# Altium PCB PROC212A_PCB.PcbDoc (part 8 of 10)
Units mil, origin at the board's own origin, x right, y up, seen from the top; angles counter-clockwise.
Board outline 3032.48 x 3598.78 mil, 4 copper layers (Top Layer, L2_GND1, L3_PWR1, Bottom Layer), stack 60.58 mil thick; 432 components, 310 nets, 7775 pads, 1236 vias.
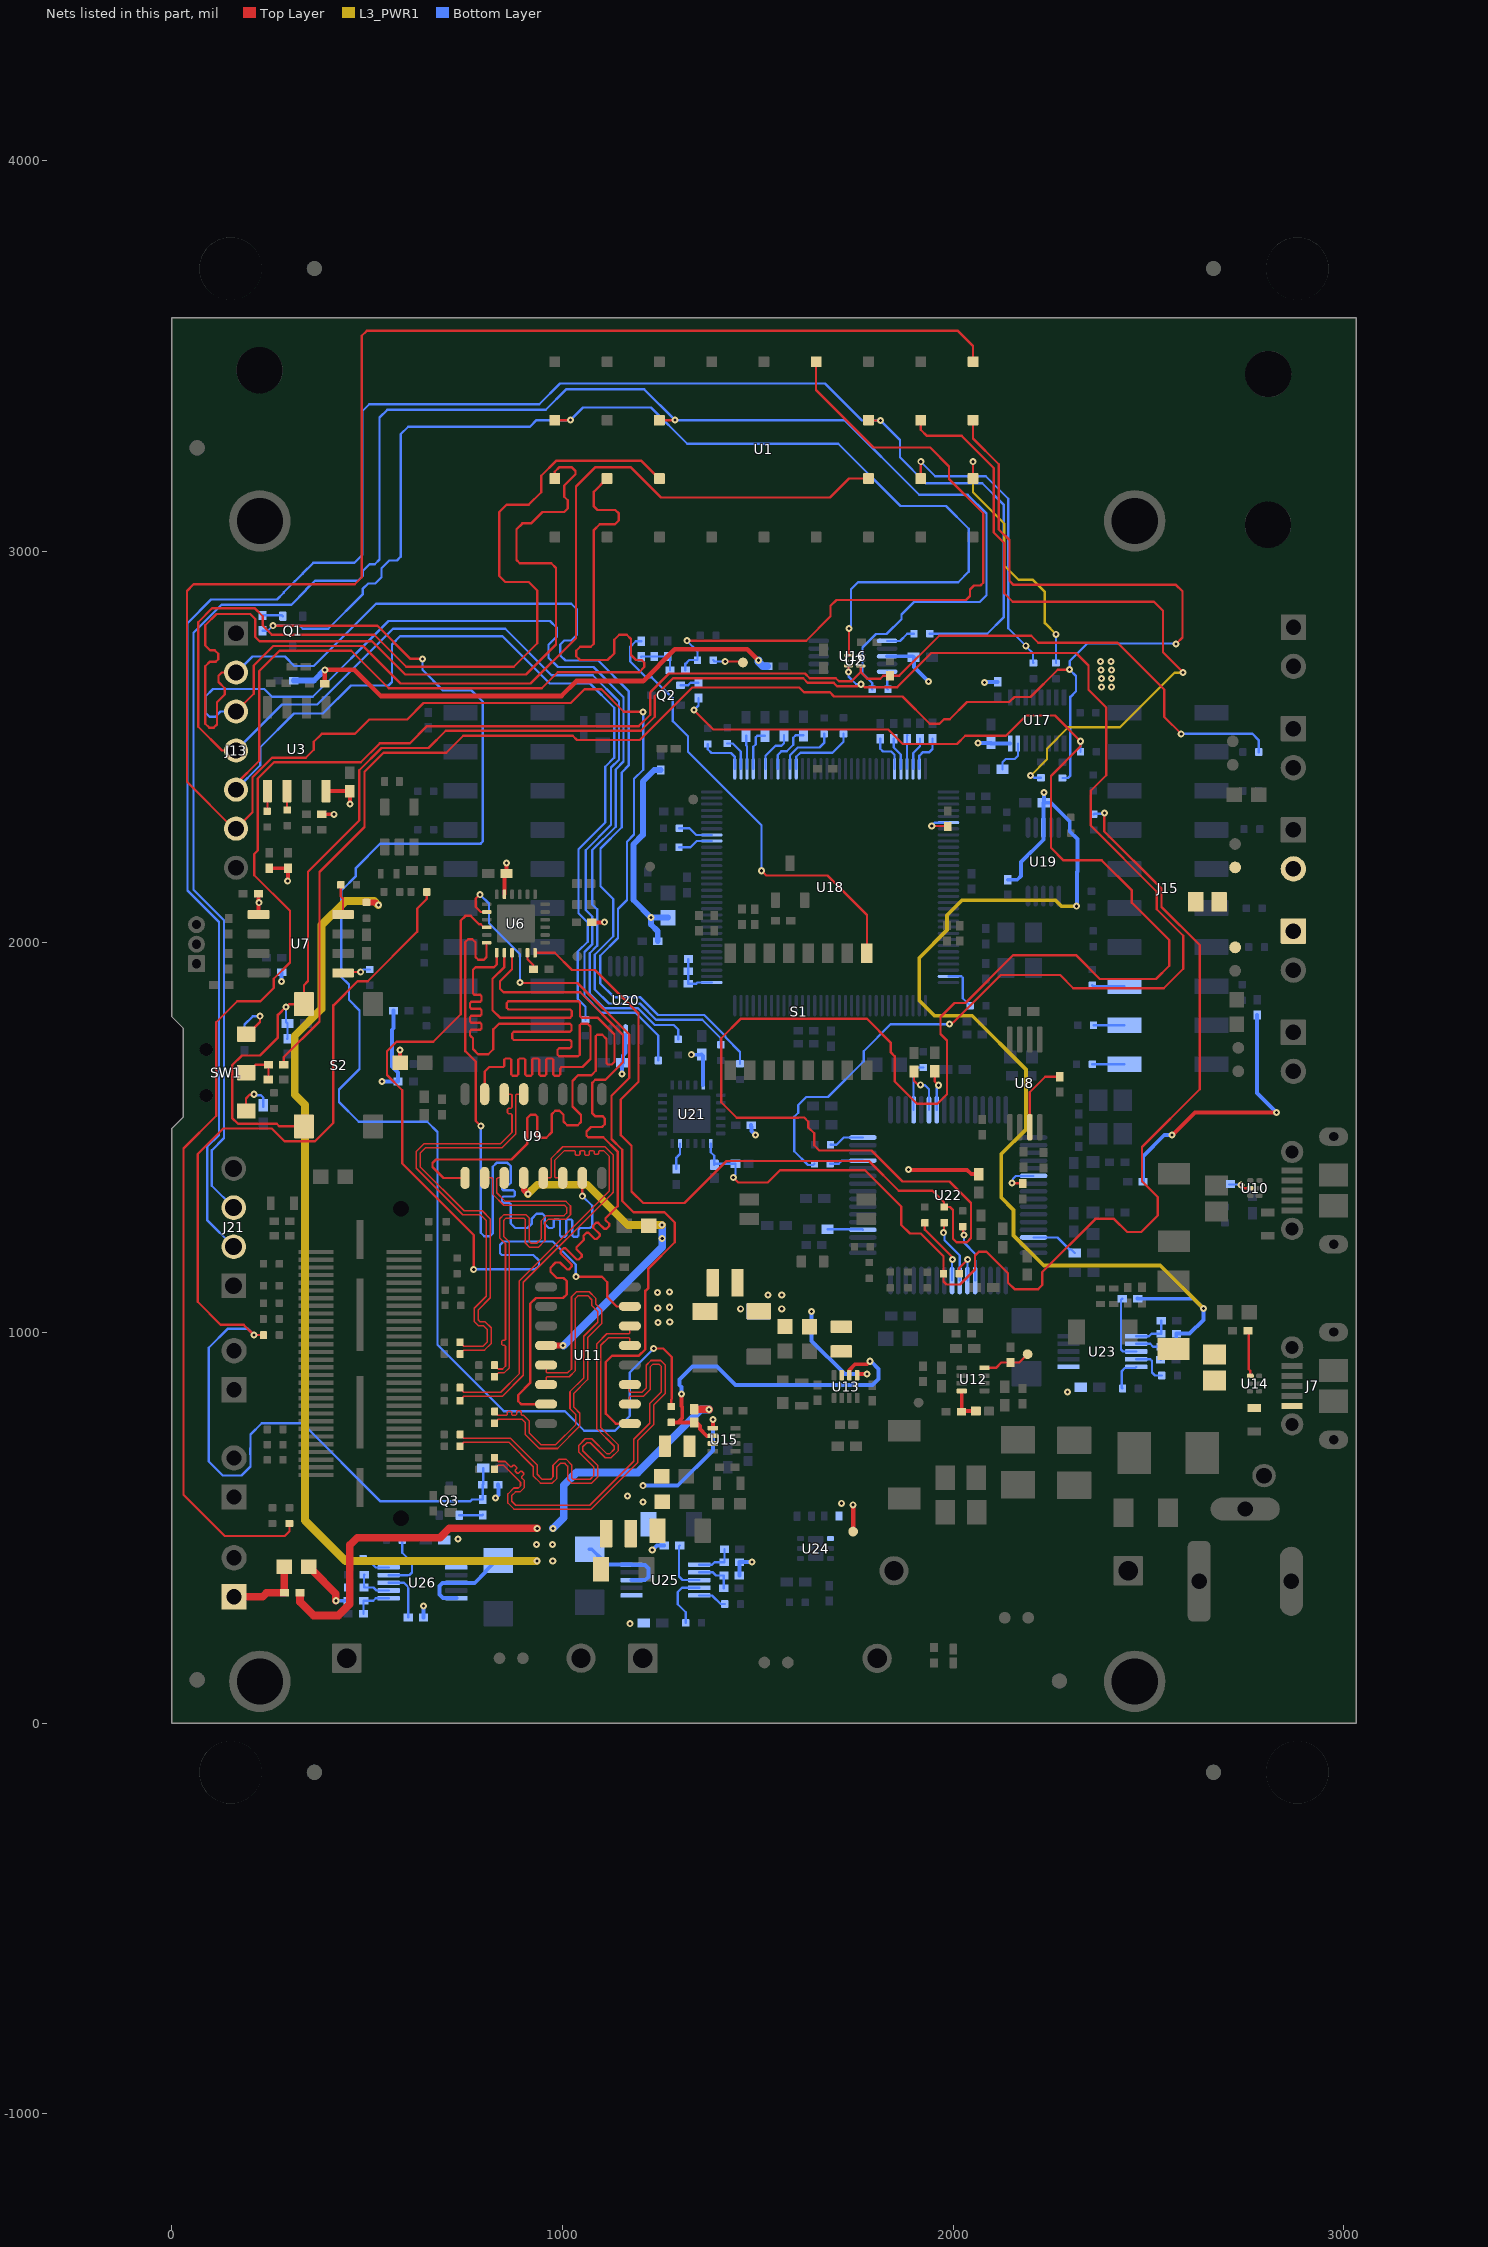
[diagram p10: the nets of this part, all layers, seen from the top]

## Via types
v1: diameter 18, hole 8, Top Layer to Bottom Layer, tented both sides, 1224 vias
v2: diameter 19.68, hole 7.87, Top Layer to Bottom Layer, tented both sides, 10 vias
v3: diameter 19.68, hole 7.87, Top Layer to Bottom Layer, 2 vias

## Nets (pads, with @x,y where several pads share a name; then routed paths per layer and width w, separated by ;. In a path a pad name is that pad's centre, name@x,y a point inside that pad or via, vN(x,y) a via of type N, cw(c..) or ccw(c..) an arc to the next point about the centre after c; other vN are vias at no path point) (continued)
NetJ15_15: J15.15 R156.2 | length 83.3
  Bottom Layer w5.9: R156.2@2356.43,1889.43 2358.64,1887.22 J15.15@2438.83,1887.22
NetJ15_17: J15.17 R163.2 | length 79.1
  Bottom Layer w5.9: R163.2@2359.71,1787.22 J15.17@2438.83,1787.22
NetJ15_19: J15.19 R173.2 | length 82.3
  Bottom Layer w5.9: R173.2@2356.49,1687.21 J15.19@2438.83,1687.22
NetJ24_1: J24.1 L7.1 R92.1 | length 200.5
  Top Layer w20: J24.1@158.99,323.6 232.19,323.6 242.44,333.86 288.16,333.86 L7.1@288.32,334.01 287.71,334.62 R92.1@287.71,400.57
NetQ1_1: Q1.1 R96.1 | length 52.8
  Bottom Layer w5.9: R96.1@231.93,2836.45 281.94,2836.45 Q1.1@283.94,2834.44
NetQ2_1: Q2.1 R109.1 | length 48.4
  Bottom Layer w5.9: Q2.1@1302.39,2657.8 1321.63,2657.8 1327.71,2663.87 1347.33,2663.87 R109.1@1348.02,2664.55
NetQ3_1: Q3.1 R203.2 | length 60.2
  Bottom Layer w5.9: Q3.1@735.68,532.71 794.84,532.71 R203.2@795.54,533.42
NetR5_1: R5.1 U18.70 | length 86.9
  Top Layer w5.9: v1(1945.42,2297.41) 1985,2297.41 R5.1@1986.29,2296.12
  Bottom Layer w5.9: v1(1945.42,2297.41) 1953.9,2305.89 U18.70@1987.37,2305.89
NetR6_1: R6.1 U3.6 | length 48.3
  Top Layer w5.9: U3.6@294.65,2386.58 294.65,2338.8 R6.1@295.02,2338.42
NetR7_1: R7.1 U3.5 | length 51.9
  Top Layer w5.9: R7.1@243.74,2335.07 244.65,2335.98 U3.5@244.65,2386.58
NetR15_1: R15.1 U7.4 | length 78.5
  Top Layer w5.9: R15.1@432.28,2146.71 432.28,2117.55 438.19,2111.64 U7.4@438.19,2070.7
NetR29_2: R29.2 R31.2 SW1.2 | length 103.5
  Top Layer w5.9: SW1.2@190.18,1665.84 194.12,1665.84 210.86,1682.57 210.86,1682.82 214.31,1686.28 R29.2@246.97,1686.28 246.97,1648.55 R31.2@246.71,1648.29
NetR30_2: R30.2 U8.3 | length 182.5
  Top Layer w5.9: U8.3@2196.46,1526.03 2196.46,1615.75 2235.92,1655.22 R30.2@2272.89,1655.22
NetR39_1: R39.1 U22.23 | length 165.6
  Top Layer w5.9: v1(1975.85,1255.9) 1976.6,1256.64 1976.6,1280.72 R39.1@1977.34,1281.47
  Bottom Layer w5.9: v1(1975.85,1255.9) 1978.03,1253.73 1978.03,1236.42 2017.07,1197.37 U22.23@2017.07,1133.54
NetR40_1: R40.1 U22.24 | length 177.1
  Top Layer w5.9: R40.1@1927.81,1281.24 1927.81,1263.47 1995.76,1195.51 1995.76,1189.56 v1(1998.08,1187.24)
  Bottom Layer w5.9: U22.24@1997.38,1133.54 1997.38,1186.55 v1(1998.08,1187.24)
NetR42_1: R42.1 U22.21 | length 151.1
  Top Layer w5.9: R42.1@2024.65,1271.49 2026.27,1269.88 2026.27,1251.26 v1(2027.89,1249.64)
  Bottom Layer w5.9: v1(2027.89,1249.64) 2027.89,1230.66 2056.25,1202.3 2056.25,1184.14 2056.44,1183.95 U22.21@2056.44,1133.54
NetR52_1: R52.1 U22.22 | length 99.1
  Top Layer w5.9: R52.1@2015.84,1151.06 2015.84,1165.63 v1(2037.45,1187.24)
  Bottom Layer w5.9: U22.22@2036.75,1133.54 2036.75,1186.55 v1(2037.45,1187.24)
NetR63_2: R63.2 U14.1 | length 117.8
  Top Layer w5.9: R63.2@2755.13,1004.53 2757.07,1002.59 2757.07,906.25 2760.99,902.33 U14.1@2760.99,889.18
NetR97_1: R97.1 U16.6 | length 76.5
  Bottom Layer w5.9: U16.6@1831.11,2771.15 1864.24,2771.15 1882.62,2789.54 R97.1@1900.04,2789.54
NetR99_2: R99.2 R100.2 R101.1 R106.2 | length 105.8
  Bottom Layer w5.9: R101.1@1201.44,2730.83 1201.88,2731.28 R99.2@1235.04,2731.28 1269.8,2731.28 R100.2@1269.86,2731.22 1275.26,2725.82 R106.2@1275.26,2696.32
NetR110_1: R110.1 U16.10 | length 46
  Bottom Layer w5.9: U16.10@1831.11,2692.41 1831.11,2649.39 R110.1@1833.2,2647.3
NetR112_1: R112.1 U18.40 | length 132.6
  Bottom Layer w5.9: U18.40@1551.19,2443.77 1551.19,2479.26 1560.37,2488.44 1573.92,2488.44 1590.9,2505.43 1590.9,2523.29 1597.5,2529.89 R112.1@1616.86,2529.89
NetR113_1: R113.1 U18.38 | length 114.4
  Bottom Layer w5.9: U18.38@1519.78,2443.69 1519.78,2477.11 1545.52,2502.86 1560.8,2502.86 1566.92,2508.99 R113.1@1566.92,2529.58
NetR114_1: R114.1 U18.36 | length 108.8
  Bottom Layer w5.9: U18.36@1488.28,2443.69 1488.28,2499.91 1495.15,2506.77 1495.15,2525.12 1498.6,2528.57 R114.1@1518.21,2528.57
NetR115_1: R115.1 U18.35 | length 85.7
  Bottom Layer w5.9: R115.1@1470.11,2528.57 1470.11,2503.71 1472.4,2501.41 U18.35@1472.4,2443.82
NetR117_2: R117.2 U18.43 | length 188.2
  Bottom Layer w5.9: U18.43@1598.52,2443.69 1598.54,2474.3 1609.22,2484.97 1691.35,2484.97 1719.52,2513.15 R117.2@1719.52,2533.72
NetR118_2: R118.2 U18.42 | length 158.4
  Bottom Layer w5.9: U18.42@1582.52,2443.93 1582.52,2478.54 1602.09,2498.1 1658.22,2498.1 1669.81,2509.69 R118.2@1669.81,2533.34
NetR119_1: R119.1 U18.61 | length 86.2
  Bottom Layer w5.9: U18.61@1881.9,2443.77 1881.9,2528.38 R119.1@1882.99,2529.47
NetR120_1: R120.1 U18.62 | length 84
  Bottom Layer w5.9: U18.62@1898.01,2443.97 1898.01,2483.91 1915.24,2501.14 R120.1@1915.24,2520.87
NetR121_1: R121.1 U18.63 | length 100.5
  Bottom Layer w5.9: U18.63@1913.71,2443.93 1913.71,2477.23 1922.93,2486.44 1939.57,2486.44 1947.45,2494.32 R121.1@1947.45,2520.66
NetR122_1: R122.1 U18.60 | length 84.2
  Bottom Layer w5.9: R122.1@1848.12,2520.45 1848.12,2498.21 1866.19,2480.14 U18.60@1866.23,2443.69
NetR123_2: R123.2 U18.59 | length 103.8
  Bottom Layer w5.9: R123.2@1813.42,2520.34 1813.42,2494.93 1820.59,2487.77 1841.73,2487.77 1850.08,2479.43 1850.08,2469.12 U18.59@1850.11,2444.13
NetR124_1: R124.1 U18.34 | length 87
  Bottom Layer w5.9: R124.1@1422.04,2508.33 1435.68,2508.33 1456.21,2487.81 1456.21,2469.28 1456.41,2469.08 1456.41,2444.07 U18.34@1456.78,2443.69
NetR125_1: R125.1 U18.33 | length 121.2
  Bottom Layer w5.9: R125.1@1371.68,2506.96 1371.68,2493.88 1381.57,2483.99 1431.64,2483.99 1440.68,2474.95 1440.68,2444.05 U18.33@1440.92,2443.8
NetR131_2: R131.2 U17.15 | length 96.1
  Bottom Layer w5.9: R131.2@2126.41,2442.26 2126.41,2460.35 2134.91,2468.85 2157.78,2468.85 2166.01,2477.08 U17.15@2166.01,2508.55
NetR139_1: R139.1 U18.25 | length 89.9
  Bottom Layer w5.9: R139.1@1299.13,2291.52 1325.07,2291.52 1342.19,2274.4 U18.25@1381.98,2274.4
NetR142_1: R142.1 U18.24 | length 90.1
  Bottom Layer w5.9: R142.1@1298.47,2242.72 1327.85,2242.72 1343.77,2258.65 U18.24@1381.98,2258.65
NetR155_1: R155.1 U7.1 | length 72
  Top Layer w5.9: U7.1@438.19,1920.7 440.78,1923.3 v1(483.37,1923.3)
  Bottom Layer w5.9: v1(483.37,1923.3) 490.03,1929.96 R155.1@506.32,1929.96
NetR160_2: R160.2 U18.95 | length 117.5
  Bottom Layer w5.9: U18.95@1988.28,1912.19 2021.12,1912.19 2024.58,1908.74 2024.58,1856.11 R160.2@2043.8,1836.89
NetR165_1: R165.1 SW1.1 | length 148.3
  Top Layer w5.9: SW1.1@180.18,1764.97 194.83,1764.97 225.46,1795.6 v1(225.46,1810.24)
  Bottom Layer w5.9: R165.1@185.74,1761.73 185.74,1788.77 207.21,1810.24 v1(225.46,1810.24)
NetR176_2: R176.2 SW1.3 | length 108.5
  Top Layer w5.9: SW1.3@190.18,1567.41 189.47,1568.12 189.47,1599.76 198.56,1608.85 208.53,1608.85 v1(210.06,1610.39)
  Bottom Layer w5.9: v1(210.06,1610.39) 212.38,1608.07 227.76,1608.07 233.75,1602.07 R176.2@233.75,1578.3
NetR183_2: R183.2 U10.5 | length 57.1
  Top Layer w5.9: v1(2736.73,1377.79) 2737.45,1377.79 2745.22,1370.01 U10.5@2760.01,1370.01
  Bottom Layer w5.9: R183.2@2706.77,1379.46 2735.06,1379.46 v1(2736.73,1377.79)
NetR187_1: R187.1 U22.36 | length 90.8
  Bottom Layer w5.9: R187.1@1678.68,1264.59 1767.91,1264.59 U22.36@1769.04,1263.46
NetR191_2: R191.2 U23.3 | length 172.6
  Bottom Layer w5.9: R191.2@2433.28,1087.16 2430.11,1084 2430.11,956.63 2435.07,951.67 U23.3@2468.83,951.67
NetR193_2: R193.2 R194.1 U23.1 | length 99.9
  Bottom Layer w5.9: U23.1@2468.83,991.04 2501.72,991.04 2508.06,997.38 R194.1@2532.69,997.38 2533.25,997.94 R193.2@2533.25,1030.57
NetR195_1: R195.1 R196.2 U23.2 | length 99.5
  Bottom Layer w5.9: U23.2@2468.83,971.36 2504.76,971.36 2512.57,963.55 R195.1@2532.12,963.55 2532.12,931.62 R196.2@2531.38,930.88
NetR197_1: R197.1 U23.4 | length 99.9
  Bottom Layer w5.9: U23.4@2468.83,931.99 2504.83,931.99 2509.17,927.65 2509.17,897.9 2516.78,890.28 R197.1@2534.03,890.28
NetR198_1: R198.1 U23.5 | length 86.7
  Bottom Layer w5.9: R198.1@2434.04,857.02 2432.17,858.89 2432.17,901.95 2439.56,909.35 2465.88,909.35 U23.5@2468.83,912.3
NetR204_1: R204.1 U26.4 | length 156.4
  Bottom Layer w5.9: U26.4@554.85,379.2 608.1,379.2 614.79,385.89 614.79,411.21 589.64,436.35 R204.1@589.64,469.17
NetR206_2: R206.2 U25.3 | length 136.3
  Bottom Layer w5.9: R206.2@1299.97,455.23 1298.1,453.36 1298.1,375.38 1306.92,366.55 U25.3@1350.1,366.55
NetR207_2: R207.2 R210.1 U25.1 | length 99.9
  Bottom Layer w5.9: U25.1@1350.1,405.92 1382.99,405.92 1389.33,412.26 R210.1@1413.96,412.26 1414.52,412.81 R207.2@1414.52,445.45
NetR209_1: R209.1 U26.5 | length 74.3
  Bottom Layer w5.9: R209.1@489.65,420.9 499.84,420.9 521.86,398.88 U26.5@554.85,398.88
NetR211_2: R211.2 R215.1 U26.2 | length 101
  Bottom Layer w5.9: R215.1@491.56,347.64 515.84,347.64 523.64,339.83 U26.2@554.85,339.83 ; R211.2@492.3,380.3 491.56,379.56 491.56,351.15 R215.1@495.07,347.64
NetR212_1: R212.1 R216.2 U25.2 | length 99.5
  Bottom Layer w5.9: U25.2@1350.1,386.24 1385.05,386.24 1392.86,378.43 R212.1@1413.39,378.43 1412.65,377.69 R216.2@1412.65,345.76
NetR218_1: R218.1 U25.5 | length 74.3
  Bottom Layer w5.9: U25.5@1350.1,327.18 1383.09,327.18 1405.11,305.16 R218.1@1415.3,305.16
NetR219_1: R219.1 R220.2 U26.1 | length 99.9
  Bottom Layer w5.9: R220.2@490.43,280.61 490.43,313.25 R219.1@490.99,313.8 515.62,313.8 521.96,320.14 U26.1@554.85,320.14
NetR221_2: R221.2 U26.3 | length 132.3
  Bottom Layer w5.9: U26.3@554.85,359.51 593.94,359.51 604.98,348.47 R221.2@604.98,270.83
NetR222_1: R222.1 U25.4 | length 147.2
  Bottom Layer w5.9: R222.1@1315.31,256.9 1315.31,284.03 1294.87,304.47 1294.87,335.88 1305.85,346.87 U25.4@1350.1,346.87
NRESET: R74.2 R96.2 U1.15 U2.4 | length 6837.2
  Top Layer w5.9: v1(258.31,2810.09) 526.14,2810.09 611.14,2725.09 v1(641.31,2725.09) ; U1.15@980.3,3336.41 v1(1020.21,3336.41) ; v1(1233.5,959.31) 1258.15,959.31 1279.86,937.6 1279.86,830.34 1278.6,829.07 R74.2@1278.6,810.73 ; U2.4@1732.16,2734.55 1733.18,2734.55 1733.58,2734.95 v1(1733.58,2803.12)
  Bottom Layer w5.9: R96.2@231.93,2797.08 245.29,2797.08 v1(258.31,2810.09) 326.94,2810.09 334.94,2802.09 400.31,2802.09 488.17,2889.96 488.17,2904.05 502.36,2918.24 520.64,2918.24 536.42,2934.02 536.42,2957.11 556.45,2977.14 576.29,2977.14 586.09,2986.94 586.09,3300.63 604.77,3319.3 916.6,3319.3 933.71,3336.41 v1(1020.21,3336.41) 1052.4,3368.6 1226.63,3368.6 1319.33,3275.9 1706,3275.9 1865.32,3116.58 1981.7,3116.58 2040.12,3058.16 2040.12,2948.52 2012.97,2921.37 1756.74,2921.37 1738.8,2903.43 1738.8,2811.62 1733.58,2806.4 v1(1733.58,2803.12) ; v1(641.31,2725.09) 641.31,2697.09 694.1,2644.3 767.1,2644.3 795.67,2615.73 795.67,2257.46 790.31,2252.09 533.19,2252.09 471,2189.9 471,2169.05 433.56,2131.61 433.56,1910.84 453.31,1891.09 453.31,1852.09 480.31,1825.09 480.31,1675.09 427.79,1622.58 427.79,1590.61 478.16,1540.24 653.57,1540.24 679.74,1514.07 679.74,969.21 849.82,799.13 1005.47,799.13 1055.6,748.99 1134.55,748.99 1172.35,786.8 1172.35,898.16 v1(1233.5,959.31)
NRST_FTDI: R180.1 U22.45 | length 87.2
  Bottom Layer w5.9: R180.1@1685.35,1432.23 1707.39,1432.23 1715.79,1440.63 U22.45@1769.04,1440.63
PGOOD: R16.1 R62.1 R201.2 R202.1 R203.1 | length 3114.3
  Top Layer w5.9: R62.1@234.25,993.83 210,993.83 v1(209.86,993.96) 183.56,1020.27 124.63,1020.27 66.03,1078.86 66.03,1457.38 131.39,1522.75 255.82,1522.75 288.86,1489.71 365.56,1489.71 413.37,1537.52 413.37,1837.9 475.45,1899.98 501.22,1899.98 627.72,2026.47 627.72,2085.46 652.59,2110.33 R16.1@652.59,2128.4
  Bottom Layer w5.9: v1(209.86,993.96) 193.49,1010.34 143.25,1010.34 94.16,961.25 94.16,670.4 130.27,634.3 177.98,634.3 200.92,657.24 200.92,688.91 200.82,689.01 200.82,703.88 200.92,703.97 200.92,739.14 229.72,767.93 334.03,767.93 534.01,567.96 763.58,567.96 768.41,572.79 R203.1@795.54,572.79 795.74,572.98 R202.1@795.74,610.79 797.12,612.18 R201.2@797.12,653.22
PMIC_CLK_OUT: R102.2 TP1.1 | length 78.5
  Top Layer w5.9: v1(1416.62,2718.66) 1459.22,2718.66 TP1.1@1462.02,2715.86
  Bottom Layer w5.9: R102.2@1386.04,2722.01 1389.4,2718.66 v1(1416.62,2718.66)
PMIC_CLK_OUT_SOP1: R102.1 R106.1 U1.4 | length 1786.3
  Top Layer w5.9: v1(1318.33,2771.66) 1623.87,2771.66 1686.31,2834.09 1686.31,2861.09 1701.31,2876.09 2033.31,2876.09 2043.36,2886.14 2043.36,2902.53 2053.87,2913.04 2070.26,2913.04 2077.31,2920.09 2077.31,3097.86 1989.62,3185.55 1989.62,3217.78 1941.31,3266.09 1796.31,3266.09 1649.16,3413.24 1649.16,3485.58 U1.4@1649.59,3486.02
  Bottom Layer w5.9: R106.1@1314.63,2696.32 1314.63,2712.34 1324.31,2722.01 R102.1@1345.69,2722.01 1345.69,2744.3 v1(1318.33,2771.66)
PRESENCE_INDICATION_GPIO: R39.2 R109.2 R126.1 U6.18 | length 6491.7
  Top Layer w5.9: U6.18@929.94,1972.77 980,1972.77 1024.02,1928.75 1083.19,1928.75 1194.77,1817.17 1194.77,1642.35 1149.33,1596.91 1149.33,1505.75 1176.78,1478.31 1176.78,1361.6 1206.48,1331.89 1312.23,1331.89 1419.79,1439.45 1784.48,1439.45 1860.71,1363.23 1947.3,1363.23 1976.86,1333.67 1976.86,1322.3 R39.2@1977.34,1321.82 1992.31,1321.82 2000.01,1314.13 2000.01,1240.32 2008.63,1231.69 2035.32,1231.69 2045.84,1242.21 2045.84,1331.98 1990.79,1387.03 1870.57,1387.03 1791.12,1466.48 1657.62,1466.48 1644.28,1479.82 1644.28,1510.77 1629.45,1525.59 1629.45,1540.15 1618.93,1550.66 1604.06,1550.66 1603.41,1550.01 1446.11,1550.01 1406.37,1589.76 1406.37,1753.6 1456.81,1804.04 1779.05,1804.04 1840.05,1743.04 1840.05,1718.29 1850.36,1707.98 1850.36,1643.53 1908.15,1585.74 1959.65,1585.74 1984.39,1610.47 1984.39,1748.07 1967.68,1764.78 1967.68,1808.11 2003.4,1843.83 2031.56,1843.83 2154.35,1966.62 2314.65,1966.62 2375.57,1905.7 2519.55,1905.7 2553.37,1939.52 2553.37,2005.12 2457.83,2100.66 2457.83,2132.19 2380.79,2209.23 2282.77,2209.23 2250.58,2241.42 2250.58,2425.31 2326.5,2501.23 2326.5,2515.09 2325.65,2515.09 2260.75,2579.98 2187.08,2579.98 2135.26,2528.16 2031.38,2528.16 2010.22,2507.01 1871.39,2507.01 1833.99,2544.41 1385.73,2544.41 v1(1336.34,2593.8)
  Bottom Layer w5.9: v1(1336.34,2593.8) 1348.02,2605.48 R109.2@1348.02,2625.18 ; R126.1@2326.42,2487.22 2326.42,2514.16 v1(2326.5,2514.24)
RADAR_LVDS_0M: R87.2 U11.11 | length 1012.5
  Top Layer w4: R87.2@826.12,650.09 826.12,650.58 835.63,660.09 849.56,660.09 892.44,617.21 892.44,607.64 886.99,602.18 875.36,602.18 860.22,587.05 860.22,563.92 875.86,548.28 1073.69,548.28 1192.13,666.72 1192.13,723.13 1233.1,764.1 1233.1,814.24 1263.15,844.29 1263.15,917.18 1251.56,928.77 1226.59,928.77 1214.23,916.41 1214.23,858.23 1203.41,847.41 1173.64,847.41 1171.3,849.75 1171.3,865.9 U11.11@1172.48,867.07
RADAR_LVDS_0P: R85.2 U11.10 | length 1012.5
  Top Layer w4: R85.2@826.12,680.09 826.12,679.6 835.63,670.09 853.71,670.09 859.44,664.36 866.87,656.92 870.27,656.92 873.85,660.5 877.24,660.5 882.33,655.41 882.33,652.01 878.75,648.44 878.75,645.04 883.84,639.95 887.24,639.95 892.33,645.04 895.72,645.04 900.81,639.95 900.81,636.56 895.72,631.47 895.72,628.07 902.44,621.35 902.44,610.19 902.44,603.49 891.13,592.18 879.5,592.18 870.22,582.9 870.22,568.07 880,558.28 1069.54,558.28 1182.13,670.86 1182.13,727.27 1223.1,768.25 1223.1,818.38 1253.15,848.43 1253.15,913.04 1247.41,918.77 1230.73,918.77 1224.23,912.27 1224.23,854.09 1207.55,837.41 1173.64,837.41 1171.3,835.06 1171.3,818.25 U11.10@1172.48,817.07
RADAR_LVDS_1M: R83.2 U11.13 | length 1100.4
  Top Layer w4: R83.2@737.69,709.15 737.69,709.64 747.2,719.15 863.11,719.15 925.36,656.9 925.36,633.11 943.6,614.87 973.97,614.87 985.66,626.56 985.66,656.36 994.62,665.32 1005.91,665.32 1009.8,661.43 1013.32,657.91 1013.32,624.53 1022.98,614.87 1075.15,614.87 1090.43,630.14 1090.43,659.66 1052.14,697.94 1052.14,707.86 1062.6,718.32 1070.79,718.32 1109.6,679.51 1124.47,679.51 1142.23,697.27 1142.23,713.31 1098.14,757.41 1098.14,967.52 1117.69,987.07 1130.05,987.07 1170.14,987.07 1172.48,984.73 U11.13@1172.48,967.07
RADAR_LVDS_1P: R81.2 U11.14 | length 1100.4
  Top Layer w4: R81.2@737.69,739.15 737.69,738.65 747.2,729.15 867.25,729.15 935.36,661.04 935.36,637.25 947.74,624.87 969.82,624.87 975.66,630.7 975.66,660.5 990.47,675.32 1010.06,675.32 1023.32,662.05 1023.32,628.67 1027.12,624.87 1071.01,624.87 1080.43,634.28 1080.43,655.52 1042.14,693.8 1042.14,712 1058.45,728.32 1074.93,728.32 1113.74,689.51 1120.32,689.51 1132.23,701.41 1132.23,709.17 1088.14,753.26 1088.14,971.66 1113.55,997.07 1134.19,997.07 1170.14,997.07 1172.48,999.42 U11.14@1172.48,1017.07
RADAR_LVDS_2M: R71.2 U9.5 | length 1097.2
  Top Layer w4: R71.2@737.7,827.41 737.7,827.9 747.2,837.41 846.22,837.41 899.79,890.98 899.79,1013.42 899.79,1128.86 1124.27,1353.34 1130.13,1359.2 1130.13,1454.92 1108.86,1476.19 1100.93,1476.19 1016.34,1476.19 1000.91,1476.19 970.64,1445.92 970.64,1398.55 968.3,1396.21 U9.5@950.64,1396.21
RADAR_LVDS_2P: R69.2 U9.6 | length 1097.2
  Top Layer w4: R69.2@737.7,857.41 737.7,856.92 747.2,847.41 842.08,847.41 889.79,895.12 889.79,1009.27 889.79,1133.01 1120.13,1363.34 1120.13,1450.77 1104.72,1466.19 1100.93,1466.19 1095.14,1466.19 1092.74,1463.79 1092.74,1459.3 1090.34,1456.9 1083.14,1456.9 1080.74,1459.3 1080.74,1463.79 1078.34,1466.19 1071.14,1466.19 1068.74,1463.79 1068.74,1456.59 1066.34,1454.19 1059.14,1454.19 1056.74,1456.59 1056.74,1463.79 1054.34,1466.19 1047.14,1466.19 1044.74,1463.79 1044.74,1456.59 1042.34,1454.19 1035.14,1454.19 1032.74,1456.59 1032.74,1463.79 1030.34,1466.19 1016.34,1466.19 1005.05,1466.19 980.64,1441.78 980.64,1398.55 982.99,1396.21 U9.6@1000.64,1396.21
RADAR_LVDS_3M: R68.2 U9.3 | length 1011.8
  Top Layer w4: R68.2@826.12,886.96 826.12,887.45 835.63,896.96 850.49,896.96 863.98,910.45 863.98,1231.62 849.32,1246.28 849.32,1287.38 854.32,1292.38 901.98,1292.38 904.36,1290.01 904.36,1229.92 915.48,1218.8 938.26,1218.8 955.2,1235.74 955.2,1282.05 963,1289.85 1008.08,1289.85 1020.42,1302.19 1020.42,1324.53 1009,1335.95 853.84,1335.95 831.81,1357.99 831.81,1393.87 834.15,1396.21 850.18,1396.21 U9.3@850.41,1395.98
RADAR_LVDS_3P: R67.2 U9.2 | length 1011.9
  Top Layer w4: U9.2@800.64,1396.21 819.46,1396.21 821.81,1393.87 821.81,1353.85 849.7,1325.95 1004.86,1325.95 1010.42,1320.39 1010.42,1306.33 1003.94,1299.85 958.86,1299.85 945.2,1286.2 945.2,1239.89 934.11,1228.8 919.63,1228.8 914.36,1234.07 914.36,1294.15 906.12,1302.38 850.18,1302.38 839.32,1291.52 839.32,1242.14 853.98,1227.47 853.98,996.55 853.98,982.55 851.58,980.15 846.45,980.15 844.05,977.75 844.05,970.55 846.45,968.15 851.58,968.15 853.98,965.75 853.98,951.77 853.98,914.59 846.35,906.96 835.63,906.96 826.12,916.47 R67.2@826.12,916.96
RADAR_LVDS_CLK: U6.15 U11.7 | length 2077.4
  Top Layer w5.9: U6.15@870.89,1972.77 870.89,1930.58 840.15,1899.84 840.15,1880.73 849.17,1871.71 1045.5,1871.71 1154.95,1762.27 1154.95,1692.07 1110.15,1647.27 1083.82,1647.27 1076.44,1639.89 1076.44,1561.47 1083.48,1554.43 1102.43,1554.43 1108.28,1548.57 1108.28,1533.56 1101.27,1526.54 1072.61,1526.54 1061.25,1515.18 1061.25,1504.76 1065.86,1500.15 1104.45,1500.15 1141.08,1463.52 1141.08,1323.86 1123.18,1305.97 1110.2,1292.98 1110.28,1287.92 1119.94,1278.59 1120.03,1273.53 1112.56,1265.81 1107.5,1265.72 1091.13,1281.54 1086.06,1281.45 1078.6,1273.73 1078.69,1268.66 1095.07,1252.84 1095.15,1247.78 1087.69,1240.06 1082.63,1239.97 1066.25,1255.79 1061.19,1255.7 1053.73,1247.98 1053.82,1242.92 1054.41,1242.35 1054.5,1237.28 1052.41,1235.2 1049.54,1232.33 1035.64,1218.43 1035.64,1213.37 1049.23,1199.77 1049.23,1194.71 1041.64,1187.11 1036.58,1187.11 1007.83,1215.86 1002.77,1215.86 995.18,1208.26 995.18,1203.2 1023.92,1174.46 1023.92,1169.39 1016.33,1161.8 1011.26,1161.8 ; U11.7@957.91,817.07 893.81,817.07 886.56,824.33 886.56,840.46 917.09,870.99 917.09,1073.81 931.9,1088.62 1001.37,1088.62 1011.21,1098.47 1011.21,1131.6 1002.82,1139.99 985.29,1139.99 969.06,1156.21 969.06,1166.46 982.35,1179.74 993.8,1179.74 1011.26,1162.29
RADAR_LVDS_CLKM: R78.2 U11.5 | length 1011.7
  Top Layer w4: R78.2@826.12,768.2 826.12,768.69 835.63,778.2 896.35,778.2 905,769.55 905,738.83 940.37,703.47 987.15,703.47 1044.41,760.73 1044.41,793.85 1029.24,809.02 1029.24,844.91 1064.2,879.87 1064.2,986.74 1100.08,1022.62 1100.08,1058.47 1084.72,1073.83 1084.72,1088.63 1068.52,1104.83 1036,1104.83 1022.98,1091.82 1022.98,907.01 1013.05,897.07 960.25,897.07 957.91,899.42 U11.5@957.91,917.07
RADAR_LVDS_CLKP: R73.2 U11.6 | length 1011.7
  Top Layer w4: R73.2@826.12,798.2 826.12,797.71 835.63,788.2 855.92,788.2 858.32,790.6 858.32,795.99 860.72,798.39 867.92,798.39 870.32,795.99 870.32,790.6 872.72,788.2 879.92,788.2 882.32,790.6 882.32,797.8 884.72,800.2 891.92,800.2 894.32,797.8 894.32,790.6 896.72,788.2 900.5,788.2 910.34,778.36 914.12,774.58 915,773.69 915,742.98 944.51,713.47 983.01,713.47 1034.41,764.87 1034.41,789.71 1019.24,804.88 1019.24,849.06 1054.2,884.01 1054.2,990.89 1090.08,1026.76 1090.08,1054.33 1077.65,1066.76 1074.72,1069.68 1074.72,1084.49 1064.38,1094.83 1040.14,1094.83 1032.98,1087.67 1032.98,902.87 1017.19,887.07 960.25,887.07 957.91,884.73 U11.6@957.91,867.07
RADAR_LVDS_DATA0: U6.8 U11.9 | length 1959.8
  Top Layer w5.9: v1(788.79,2121.31) 788,2121.31 778.14,2111.46 778.14,2089.86 790.9,2077.1 U6.8@805.93,2077.1 ; v1(891.15,1896.38) 892.16,1895.37 1038.67,1895.37 1170.97,1763.08 1170.97,1652.21 1125.53,1606.77 1125.53,1495.9 1152.98,1468.45 1152.98,1336.85 1181.74,1308.09 1261,1308.09 1287.11,1281.98 1287.11,1231.31 1219.84,1164.04 1219.84,1114.56 1212.23,1106.96 1212.23,957.62 1195.82,941.2 1127.28,941.2 1110.8,924.73 1110.8,792.66 1136.39,767.07 U11.9@1172.48,767.07
  Bottom Layer w5.9: v1(788.79,2121.31) 811.54,2098.56 811.54,2048.46 891.15,1968.85 v1(891.15,1896.38)
RADAR_LVDS_DATA1: U6.10 U11.15 | length 1961.2
  Top Layer w5.9: v1(772.61,1161.45) 772.61,1250.05 589.58,1433.08 589.58,1620.51 550.5,1659.6 550.5,1720.35 575.02,1744.87 669.09,1744.87 739.19,1814.98 739.19,2054.98 751.35,2067.14 764.86,2067.14 786.24,2045.76 790.82,2045.76 798.84,2037.73 U6.10@805.93,2037.73 ; v1(1034.08,1143.18) 1100.89,1143.18 1114.8,1129.27 1114.8,1091.36 1139.09,1067.07 U11.15@1172.48,1067.07
  Bottom Layer w5.9: v1(772.61,1161.45) 773.87,1162.71 930.98,1162.71 939.7,1171.43 939.7,1184.45 925.23,1198.92 844.21,1198.92 839.97,1203.15 839.97,1224.26 849.09,1233.38 974.98,1233.38 1034.08,1174.28 v1(1034.08,1143.18)
RADAR_LVDS_DATA2: U6.12 U9.7 | length 1959.7
  Top Layer w5.9: v1(790.78,1528.76) 777.58,1541.96 777.58,1694.49 751.22,1720.84 751.22,1999.95 758.71,2007.43 769.04,2007.43 777.07,1999.41 777.07,1962.04 784.09,1955.02 798.89,1955.02 805.53,1961.66 U6.12@805.53,1997.96 ; v1(1050.63,1349.31) U9.7@1050.64,1396.21
  Bottom Layer w5.9: v1(790.78,1528.76) 790.78,1255.65 799.43,1247.01 814.49,1247.01 821.43,1253.94 821.43,1424.98 831.15,1434.71 859.25,1434.71 867.31,1426.65 867.31,1386.94 867.31,1383.66 863.85,1380.2 848.49,1380.2 845.31,1377.02 845.31,1367.48 848.49,1364.3 874.66,1364.3 877.84,1361.12 877.84,1351.58 874.66,1348.4 848.49,1348.4 845.31,1345.22 845.31,1335.68 848.49,1332.5 863.85,1332.5 867.31,1329.04 867.31,1326.09 867.31,1279.43 878.87,1267.87 910.2,1267.87 921.55,1279.22 921.55,1292.52 933.81,1304.78 948.15,1304.78 954.53,1298.4 954.53,1278.27 964.93,1267.87 973.98,1267.87 977.44,1271.32 977.44,1286.69 980.62,1289.87 990.16,1289.87 993.34,1286.69 993.34,1249.05 996.52,1245.87 1006.06,1245.87 1009.24,1249.05 1009.24,1286.69 1012.42,1289.87 1021.96,1289.87 1025.14,1286.69 1025.14,1249.05 1028.32,1245.87 1037.86,1245.87 1041.04,1249.05 1041.04,1264.41 1044.49,1267.87 1047.44,1267.87 1070.08,1267.87 1075.86,1273.65 1075.86,1324.91 1051.46,1349.31 v1(1050.63,1349.31)
RADAR_LVDS_DATA3: U6.14 U9.1 | length 2077.6
  Top Layer w5.9: U9.1@750.64,1396.21 695.07,1396.21 667.13,1424.14 667.13,1434.68 675.81,1443.35 869.5,1443.35 909.41,1483.26 909.41,1549.23 918.09,1557.9 930.51,1557.9 935.45,1552.96 935.45,1502.41 938.9,1498.95 958.49,1498.95 972.08,1512.55 972.08,1558.49 981.55,1567.96 992.17,1567.96 1002.34,1557.78 1002.34,1540.63 1012.22,1530.75 1038.88,1530.75 1047.25,1539.12 1047.25,1557.04 1025.39,1578.89 1025.39,1644.34 1039.89,1658.84 1073.89,1658.84 1085.37,1670.32 1085.37,1759.45 1088.83,1762.91 1101.93,1762.91 1112.64,1752.2 1112.64,1690.2 1116.1,1686.74 1126.13,1686.74 1133.12,1693.74 1133.12,1763.07 1089.6,1806.59 1051.91,1806.59 1048.96,1806.59 1044.78,1810.77 1044.78,1844.21 1040.6,1848.39 861.44,1848.39 857.26,1844.21 857.26,1831.67 861.44,1827.49 1019.7,1827.49 1023.88,1823.31 1023.88,1810.77 1019.7,1806.59 854.31,1806.59 839.73,1806.59 820.68,1825.65 820.68,1905.92 851.2,1936.45 U6.14@851.2,1972.77
RADAR_LVDS_FRCLK: U6.13 U9.15 | length 2077.2
  Top Layer w5.9: U9.15@800.64,1610.78 800.64,1668.54 812.15,1680.05 844.34,1680.05 847.29,1680.05 850.87,1683.63 850.87,1698.47 854.45,1702.05 865.19,1702.05 868.77,1698.47 868.77,1661.63 872.35,1658.05 883.09,1658.05 886.67,1661.63 886.67,1698.47 890.25,1702.05 900.99,1702.05 904.57,1698.47 904.57,1661.63 908.15,1658.05 918.89,1658.05 922.47,1661.63 922.47,1698.47 926.05,1702.05 936.79,1702.05 940.37,1698.47 940.37,1661.63 943.95,1658.05 954.69,1658.05 958.27,1661.63 958.27,1698.47 961.85,1702.05 972.59,1702.05 976.17,1698.47 976.17,1661.63 979.75,1658.05 990.49,1658.05 994.07,1661.63 994.07,1676.47 997.65,1680.05 1014.59,1680.05 1051.23,1680.05 1071.81,1700.62 1071.81,1783.65 1064.32,1791.14 1051.08,1791.14 1048.13,1791.14 1043.95,1786.96 1043.95,1711.72 1039.77,1707.54 991.59,1707.54 987.41,1711.72 987.41,1724.26 991.59,1728.44 1018.87,1728.44 1023.05,1732.62 1023.05,1745.16 1018.87,1749.34 875.25,1749.34 871.07,1753.52 871.07,1766.06 875.25,1770.24 1018.87,1770.24 1023.05,1774.42 1023.05,1786.96 1018.87,1791.14 868.12,1791.14 837.42,1791.14 822.8,1776.52 822.8,1725.59 810.09,1712.88 783.8,1712.88 770.73,1725.95 770.73,1751.05 770.73,1754 767.15,1757.58 766.7,1757.58 763.12,1761.16 763.12,1771.9 766.7,1775.48 789.15,1775.48 792.73,1779.06 792.73,1789.8 789.15,1793.38 766.7,1793.38 763.12,1796.96 763.12,1807.7 766.7,1811.28 789.15,1811.28 792.73,1814.86 792.73,1825.6 789.15,1829.18 766.7,1829.18 763.12,1832.76 763.12,1843.5 766.7,1847.08 789.15,1847.08 792.73,1850.66 792.73,1861.4 789.15,1864.98 774.31,1864.98 770.73,1868.56 770.73,1882.4 770.73,1929.03 777.11,1935.42 824.33,1935.42 831.52,1942.6 U6.13@831.52,1972.77
RADAR_LVDS_FRCLKM: R66.2 U9.13 | length 1100
  Top Layer w4: R66.2@737.7,945.34 737.7,945.83 747.2,955.34 800.58,955.34 817.24,972 817.24,1012.25 801.36,1028.13 788.59,1028.13 783.99,1032.73 783.99,1058.28 814.97,1089.26 814.97,1243.15 814.97,1291.25 794.34,1311.87 748.41,1311.87 635.34,1424.95 635.34,1459.51 649.34,1473.51 845.19,1473.51 880.64,1508.96 880.64,1513.11 880.64,1555.69 880.64,1587.66 880.64,1608.44 882.99,1610.78 U9.13@900.64,1610.78
RADAR_LVDS_FRCLKP: R64.2 U9.14 | length 1100
  Top Layer w4: R64.2@737.7,975.34 737.7,974.85 747.2,965.34 796.44,965.34 807.24,976.15 807.24,1008.11 797.22,1018.13 784.45,1018.13 773.99,1028.59 773.99,1062.42 804.97,1093.4 804.97,1243.15 804.97,1287.1 790.2,1301.88 744.27,1301.88 625.34,1420.81 625.34,1463.65 645.2,1483.51 841.05,1483.51 870.64,1513.11 870.64,1555.69 870.64,1557.69 867.84,1560.49 861.88,1560.49 859.08,1563.29 859.08,1571.69 861.88,1574.49 867.84,1574.49 870.64,1577.29 870.64,1583.51 870.64,1608.44 868.3,1610.78 U9.14@850.64,1610.78
RADAR_NRST_1: R2.1 R90.1 R127.2 U2.1 | length 5339.8
  Top Layer w5.9: R90.1@300.86,511.37 300.86,491.37 288.66,479.18 135.32,479.18 29.49,585.01 29.49,1471.33 113.51,1555.35 113.51,1794.59 167.42,1848.5 226.78,1848.5 260.69,1882.41 260.69,1906.11 302.08,1947.5 302.08,2080.19 210.94,2171.33 210.94,2225.76 219.95,2234.77 219.95,2418.73 261.41,2460.19 483.3,2460.19 531.9,2508.79 609.01,2508.79 653.16,2552.94 1195.27,2552.94 1224.39,2582.06 1224.39,2637.48 1225.16,2638.24 1225.16,2640.09 1272.58,2687.51 1621.12,2687.51 1633.09,2675.53 1699.86,2675.53 1707.71,2667.69 1740.26,2667.69 1763.78,2691.2 ; U2.1@1763.78,2706.99 1763.78,2691.2 ; v1(2584.07,2533.23) 2540.85,2576.44 2540.85,2646.41 2420.8,2766.47 2218.16,2766.47 2200.13,2784.5 1964.66,2784.5 1861.89,2681.73 R2.1@1838.44,2681.73 1821.09,2681.73 1813.77,2674.41 1780.57,2674.41 1763.78,2691.2
  Bottom Layer w5.9: v1(2584.07,2533.23) 2766.39,2533.23 2782.35,2517.27 R127.2@2782.35,2485.88
RADAR_NRST_2: C68.1 R167.1 R180.2 S2.3 S2.4 U2.6 | length 5750
  Top Layer w5.9: S2.4@337.88,1528.17 274.55,1528.17 268.07,1534.65 168.98,1534.65 154.11,1549.51 154.11,1684.5 179.48,1709.87 225.61,1709.87 271.27,1755.53 271.27,1813.66 v1(291.86,1834.25) 294.29,1834.25 301.21,1841.16 S2.3@337.88,1841.16 337.88,1889.66 348.57,1900.36 348.57,2179.85 479.85,2311.13 479.85,2439.91 536.83,2496.89 657.11,2496.89 701.26,2541.04 1200.2,2541.04 1236.29,2577.13 1236.29,2629.1 1282.81,2675.61 1616.19,2675.61 1628.17,2663.63 1694.43,2663.63 1702.73,2655.33 1756.1,2655.33 1760.98,2660.21 1765.57,2660.21 1773.04,2652.74 1856.73,2652.74 1944.09,2740.1 2314.95,2740.1 2346.92,2708.13 2346.92,2645.94 2392.32,2600.53 2392.32,2427.44 2352.31,2387.42 2352.31,2298.47 2521.63,2129.15 2521.63,2084.1 2589.38,2016.36 2589.38,1931.85 2539.42,1881.9 2307.93,1881.9 2274.15,1915.68 2122.03,1915.68 2000.55,1794.19 1998.75,1794.19 1994.56,1790.01 v1(1991.29,1790.01) ; U2.6@1732.3,2706.97 1732.46,2706.81 v1(1732.46,2691.65)
  Bottom Layer w5.9: v1(291.86,1834.25) 291.86,1795.59 C68.1@295.95,1791.49 295.95,1753.36 R167.1@295.22,1752.63 ; R180.2@1645,1432.23 1642.09,1429.32 1628.37,1429.32 1593.09,1464.6 1593.09,1552.51 1603.56,1562.98 1603.56,1582.93 1624.16,1603.54 1679.48,1603.54 1771.11,1695.16 1771.11,1720.44 1840.67,1790.01 v1(1991.29,1790.01) ; v1(1732.46,2691.65) 1732.46,2679.9 1752.15,2660.21 v1(1764.25,2660.21)
REF_FTDI: R38.2 U22.6 | length 95.8
  Top Layer w5.9: v1(2151.3,1382.72) 2177.5,1382.72 R38.2@2178.64,1381.59
  Bottom Layer w5.9: v1(2151.3,1382.72) 2153.35,1384.78 2153.35,1394.22 2160.38,1401.26 U22.6@2206.05,1401.26
REG_1V8: C32.2 L2.2 R18.1
  other v1: 1244.46,1025.94 1274.62,1027.51 1243.85,1063.33 1273.72,1065.05 1243.44,1103.18 1273.72,1103.79 2380.3,2653.33 2405.67,2652.68 2379.73,2674.97 2405.19,2675.24 2378.82,2696.71 2405.44,2696.64 2377.92,2718.45 2404.53,2718.38
REG_3V3: C56.2 L6.2 L7.2 R20.2 R75.2 R205.1 R208.1 U25.8 U25.10 U26.8 U26.10 | length 4333
  Top Layer w15: R20.2@499.31,2100.55 500.42,2101.66 520.66,2101.66 527.58,2094.74 v1(528.39,2094.74)
  Top Layer w20: L7.2@327.69,334.01 327.69,310.71 362.31,276.09 426.31,276.09 455.31,305.09 455.31,456.09 474.31,475.09 686.31,475.09 710.18,498.97 v1(935.2,498.97) ; R75.2@1337.07,803.94 1374.23,803.94 v1(1375.18,802.98)
  L3_PWR1 w20: v1(528.39,2094.74) 517.96,2105.17 444.61,2105.17 383,2043.55 383,1828.98 314.29,1760.27 314.29,1609.83 340.82,1583.31 340.82,519.12 444.37,415.56 v1(934.25,415.56)
  Bottom Layer w10: U26.10@728.08,320.14 727.53,320.69 694.1,320.69 684.8,329.99 684.8,351.2 693.11,359.51 U26.8@728.08,359.51 775.33,359.51 802.52,386.7 802.52,389.01 830,416.49 R208.1@835.51,416.49 ; R205.1@1069.44,445.4 1074.95,445.4 1102.43,417.92 1102.43,417.49 1114,405.92 U25.10@1176.87,405.92 1177.42,405.37 1210.85,405.37 1220.15,396.07 1220.15,374.86 1211.84,366.55 U25.8@1176.87,366.55
  Bottom Layer w20: v1(975.95,498.97) 1003.14,526.16 1003.14,609.08 1035.85,641.79 1193.04,641.79 1354.23,802.98 v1(1375.18,802.98)
  other v1: 975,415.56 933.77,457.5 974.53,457.5
REG_OUT_1V8: C33.2 C35.1 C36.1 C88.2 L2.1 L3.2 U13.5 | length 278.2
  Top Layer w10: U13.5@1754.21,890.95 1756.93,893.67 v1(1779.19,893.67)
  Bottom Layer w10: v1(1637.97,1054.54) 1637.97,979.06 1723.36,893.67 v1(1779.19,893.67)
  other v1: 1456.31,1061.09 1561.31,1061.09 1526.31,1096.09 1561.31,1096.09
REG_OUT_3V3: C51.1 C53.1 C55.2 C94.2 L5.2 L6.1 U15.5 | length 318.3
  Top Layer w10: U15.5@1384.83,755.53 1385.04,755.74 v1(1385.04,777.86)
  Bottom Layer w10: v1(1206.15,608.16) 1295.02,608.16 1385.04,698.17 v1(1385.04,777.86)
  other v1: 1205.68,566.18 1166.21,582.09
REG_PG: R74.1 R75.1 U13.6 U15.6 | length 917.3
  Top Layer w10: R74.1@1278.6,770.38 1295.47,770.38 ; v1(1304.52,843.14) 1304.52,812.23 1306.55,810.2 1306.55,781.46 1295.47,770.38 ; R75.1@1337.07,770.38 1295.47,770.38 ; R75.1@1343.04,770.38 1351.91,761.51 1351.91,753.21 1369.27,735.85 U15.6@1384.83,735.85 ; U13.6@1734.53,890.95 1734.53,904.43 1749.14,919.04 1779.9,919.04 v1(1787.67,926.81)
  Bottom Layer w10: v1(1304.52,843.14) 1304.52,860.37 1299.49,865.4 1299.49,880.2 1333.15,913.86 1395.17,913.86 1442.77,866.26 1793.65,866.26 1809.09,881.7 1809.09,907.07 1789.35,926.81 v1(1787.67,926.81)
RS232_FTDI_RX: R178.1 U22.48 | length 91.8
  Bottom Layer w5.9: R178.1@1685.97,1481.37 R178.1@1686.46,1481.37 ; R178.1@1687.3,1482.21 R178.1@1686.46,1481.37 ; U22.48@1769.04,1499.68 1719.94,1499.68 1701.63,1481.37 R178.1@1686.46,1481.37
RS232_FTDI_TX: R170.1 U22.52 | length 128.2
  Bottom Layer w5.9: U22.52@1898.96,1570.55 1898.9,1627.08 1898.83,1627.15 1898.83,1642.02 1898.9,1642.09 1898.9,1670.3 1907.48,1678.88 R170.1@1923.81,1678.88
RS232_RX_UARTB_RX: J21.2 R97.2 U1.12 | length 4910.9
  Top Layer w5.9: U1.12@1783.45,3336.41 1784.52,3335.34 v1(1813.91,3335.34)
  Bottom Layer w5.9: J21.2@158.04,1220.16 90.04,1288.16 90.04,1476.09 120.31,1506.35 120.31,2051.23 39.61,2131.93 39.61,2816.63 100.12,2877.14 268.74,2877.14 286.31,2894.71 286.31,2895.48 314.45,2923.62 315.22,2923.62 334.54,2942.95 334.54,2943.72 362.1,2971.27 363.59,2971.27 ; 363.59,2971.26 467.34,2971.26 487.49,2991.42 487.49,3359.11 505.38,3377 940.55,3377 993.51,3429.96 1671.89,3429.96 1766.51,3335.34 v1(1813.91,3335.34) 1863.98,3285.27 1863.98,3241.23 1930.14,3175.07 2074.61,3175.07 2129.41,3120.28 2129.41,2831.39 2087.55,2789.54 R97.2@1940.4,2789.54
RS232_TX_UARTB_TX: J21.3 R110.2 U1.13 | length 4930.5
  Top Layer w5.9: U1.13@1244.78,3336.41 U1.13@1248.02,3336.41 v1(1287.93,3336.41)
  Bottom Layer w5.9: J21.3@158.04,1320.16 101.94,1376.26 101.94,1466.72 133.31,1498.08 133.31,2055.94 55.19,2134.05 55.19,2792.15 126.95,2863.91 305.9,2863.91 343.32,2901.34 343.32,2902.49 366.16,2925.33 378.27,2925.33 ; 378.27,2925.28 476.59,2925.28 489.17,2937.85 489.17,2950.67 505.78,2967.29 519.24,2967.29 531.67,2979.72 531.67,3343.27 551.65,3363.25 957.19,3363.25 1009.12,3415.17 1209.17,3415.17 v1(1287.93,3336.41) 1722.21,3336.41 1913.3,3145.32 2037.27,3145.32 2085.39,3097.2 2085.39,2888.13 2068.23,2870.97 1900.23,2870.97 1867.72,2838.47 1867.72,2826.8 1829.68,2788.76 1802.85,2788.76 1768.2,2754.12 1768.2,2687.94 1792.85,2663.3 R110.2@1792.85,2647.3
RST_FTDI: R189.2 U22.14 | length 122.1
  Bottom Layer w5.9: U22.14@2206.05,1243.77 2267.25,1243.77 2298.07,1212.95 2302.82,1212.95 R189.2@2311.68,1204.09
SOP0_FTDI: R26.1 U22.55 | length 104.4
  Top Layer w5.9: R26.1@1952.84,1669.12 1952.84,1643.1 v1(1962.5,1633.44)
  Bottom Layer w5.9: U22.55@1958.01,1570.55 1958.01,1625.68 1962.5,1630.17 v1(1962.5,1633.44)
SOP1_FTDI: R27.1 U22.54 | length 123.7
  Top Layer w5.9: R27.1@1900.18,1668.76 1900.18,1644.98 1908.26,1636.9 1914.46,1636.9 v1(1916.78,1634.59)
  Bottom Layer w5.9: v1(1916.78,1634.59) 1918.02,1633.35 1928.28,1633.35 1938.33,1623.3 U22.54@1938.33,1570.55
SOP1_SW: R101.2 S1.1 | length 1169.3
  Top Layer w5.9: v1(1509.67,2182.66) 1521.9,2170.43 1678.68,2170.43 1779.42,2069.69 S1.1@1779.42,1971.82
  Bottom Layer w5.9: R101.2@1201.44,2770.2 1187.44,2770.2 1173.1,2755.87 1173.1,2719.27 1214.63,2677.75 1228.31,2677.75 1282.63,2623.43 1282.63,2565.55 1321.27,2526.91 1321.27,2487.26 1509.39,2299.15 1509.39,2182.94 v1(1509.67,2182.66)
SPI_BUSY/SPI_HOST_INTR: J13.6 R174.2 U1.1 | length 5853.1
  Top Layer w5.9: v1(1206.44,2589.5) 1157.08,2589.5 1099.48,2647.09 1056.31,2647.09 1021.31,2612.09 644.31,2612.09 602.31,2570.09 505.31,2570.09 468.26,2533.04 383.31,2533.04 362.93,2512.66 362.93,2492.47 342.55,2472.09 256.48,2472.09 206.37,2421.99 206.37,2332.6 J13.6@164.16,2290.39 158.2,2290.39 38.31,2410.28 38.31,2899.09 55.31,2916.09 468.31,2916.09 486.19,2933.97 486.19,3552.44 498.71,3564.97 2012.64,3564.97 2051.17,3526.44 U1.1@2051.17,3486.02
  Bottom Layer w5.9: v1(1206.44,2589.5) 1206.44,2441.23 1183.26,2418.05 1183.26,2275.27 1165.05,2257.06 1165.05,2107.68 1142.3,2084.93 1142.3,2010.42 1096.86,1964.98 1096.86,1893.88 1131.59,1859.15 1198.52,1859.15 1244.33,1813.34 1362.86,1813.34 1417.32,1758.87 1417.32,1756.16 1454.61,1718.88 R174.2@1454.61,1688.4
SPI_CLK_I2C_SCL: J13.5 R164.2 U1.20 | length 4450.1
  Top Layer w5.9: J13.5@164.16,2390.39 164.16,2404.95 223.31,2464.09 223.31,2693.81 275.54,2746.04 459.36,2746.04 555.31,2650.09 947.02,2650.09 988.02,2691.09 1196.31,2691.09 1209.31,2704.09 1209.31,2715.09 1202.31,2722.09 1188.2,2722.09 1175.31,2734.99 1175.31,2776.09 1164.31,2787.09 1145.31,2787.09 1132.31,2774.09 1132.31,2739.09 1115.31,2722.09 1044.74,2722.09 1035.03,2731.81 1035.03,2745.82 1045.31,2756.09 1072.31,2756.09 1080.31,2764.09 1080.31,3055.09 1095.31,3070.09 1134.31,3070.09 1144.31,3080.09 1144.31,3097.09 1135.31,3106.09 1089.83,3106.09 1080.31,3115.62 1080.31,3152.95 U1.20@1114.16,3186.81
  Bottom Layer w5.9: J13.5@164.16,2390.39 226.31,2452.53 226.31,2499.09 312.31,2585.09 386.31,2585.09 458.31,2657.09 554.31,2657.09 563.31,2666.09 563.31,2762.09 584.26,2783.04 846.36,2783.04 967.31,2662.09 1070.21,2662.09 1132.58,2599.73 1132.58,2472.28 1109.31,2449.01 1109.31,2306.48 1040.81,2237.98 1040.81,2073.59 1064.59,2049.81 1064.59,2000.92 1039.31,1975.64 1039.31,1854.09 1058.83,1834.57 R164.2@1058.83,1800.89
SPI_CS_I2C_SDA: J13.4 R171.2 U1.19 | length 4577.9
  Top Layer w5.9: J13.4@164.16,2490.39 128.01,2490.39 67.31,2551.09 67.31,2819.09 103.31,2855.09 211.31,2855.09 232.31,2834.09 232.31,2810.71 255.92,2787.09 518.14,2787.09 600.14,2705.09 875.31,2705.09 935.31,2765.09 935.31,2900.09 913.31,2922.09 853.31,2922.09 838.31,2937.09 838.31,3101.09 857.31,3120.09 913.46,3120.09 945.31,3151.94 945.31,3194.09 983.31,3232.09 1202.31,3232.09 1247.31,3187.09 1247.73,3187.09 U1.19@1248.02,3186.81
  Bottom Layer w5.9: J13.4@164.16,2490.39 281.87,2608.09 372.31,2608.09 566.31,2802.09 853.14,2802.09 972.14,2683.09 1077.31,2683.09 1144.48,2615.92 1144.48,2467.12 1124.31,2446.95 1124.31,2300.37 1059.31,2235.37 1059.31,2082.09 1076.49,2064.91 1076.49,1995.1 1056.35,1974.96 1056.35,1862.05 1099.47,1818.93 1186.81,1818.93 1244.91,1760.82 R171.2@1244.91,1696.9
SPI_MISO: J13.3 R168.2 U1.18 | length 4827.1
  Top Layer w5.9: J13.3@164.16,2590.39 209.58,2635.81 209.58,2708.37 259.16,2757.94 489.46,2757.94 585.41,2661.99 918.21,2661.99 1034.31,2778.09 1034.31,3166.15 1084.29,3216.13 1174.27,3216.13 1252.31,3138.09 1684.59,3138.09 1733.31,3186.81 U1.18@1783.45,3186.81
  Bottom Layer w5.9: J13.3@164.16,2590.39 124.6,2590.39 111.31,2577.09 96.31,2577.09 85.31,2588.09 85.31,2628.09 105.31,2648.09 236.31,2648.09 256.31,2628.09 360.31,2628.09 554.31,2822.09 968.31,2822.09 985.31,2805.09 985.31,2782.09 964.31,2761.09 964.31,2728.09 988.31,2704.09 1079.31,2704.09 1156.38,2627.02 1156.38,2462.2 1136.31,2442.13 1136.31,2295.54 1076.31,2235.54 1076.31,2096.09 1088.59,2083.81 1088.59,1990.37 1069.87,1971.66 1069.87,1868.34 1107.39,1830.83 1192.98,1830.83 1235.96,1787.84 1284.61,1787.84 1296.07,1776.38 R168.2@1296.07,1751.03
SPI_MOSI: J13.2 R169.2 U1.21 | length 4829.9
  Top Layer w5.9: J13.2@164.16,2690.39 127.6,2690.39 119.31,2682.09 119.31,2666 135.31,2650 135.31,2634.09 115.31,2614.09 115.31,2557.09 107.31,2549.09 95.31,2549.09 85.31,2559.09 85.31,2706.09 97.31,2718.09 112.31,2718.09 118.31,2724.09 118.31,2738.09 109.31,2747.09 97.43,2747.09 85.31,2759.22 85.31,2811.09 114.31,2840.09 200.31,2840.09 213.31,2827.09 213.31,2781.09 224.31,2770.09 512.31,2770.09 597.31,2685.09 906.31,2685.09 983.31,2762.09 983.31,2957.81 971.02,2970.09 890.31,2970.09 882.31,2978.09 882.31,3057.09 897.31,3072.09 919.31,3072.09 948.65,3101.43 1004.65,3101.43 1013.31,3110.09 1013.31,3131.09 1004.31,3140.09 1004.31,3169.09 1033.31,3198.09 1033.31,3206.09 1023.31,3216.09 992.31,3216.09 980.3,3204.09 U1.21@980.3,3186.81
  Bottom Layer w5.9: J13.2@164.16,2690.39 165.6,2690.39 206.31,2731.09 289.31,2731.09 313.31,2707.09 363.31,2707.09 522.31,2866.09 1022.31,2866.09 1036.31,2852.09 1036.31,2786.09 1022.31,2772.09 1004.31,2772.09 994.31,2762.09 994.31,2734.09 1007.31,2721.09 1091.31,2721.09 1169.31,2643.09 1169.31,2452.09 1151.5,2434.29 1151.5,2293.9 1097.31,2239.71 1097.31,2143.09 1130.02,2110.38 1130.02,2014.98 1082.66,1967.62 1082.66,1878.84 1118.77,1842.73 1198.11,1842.73 1239.4,1801.44 1357.93,1801.44 1405.42,1753.95 R169.2@1405.42,1737.01
SPI_MUX_ENn: R182.1 U21.17 | length 69.4
  Bottom Layer w5.9: R182.1@1290.96,1418.96 1290.96,1447.44 1295.69,1452.17 1295.69,1452.31 1301.03,1457.65 U21.17@1301.03,1484.16
SPI_RS232_CTRL_GPIO_3: R52.2 R138.1 R179.2 R181.1 U21.13 | length 2914.1
  Top Layer w5.9: v1(1437.27,1397.02) 1449.89,1384.4 1525.71,1384.4 1556.96,1415.65 1774.63,1415.65 1867.43,1322.85 1867.43,1275.95 1889.42,1253.95 1917,1253.95 1975.48,1195.47 R52.2@1975.48,1151.06 1975.48,1131.11 1983.14,1123.45 2018.07,1123.45 2056.35,1161.73 2056.35,1197.63 2061.55,1202.82 2061.85,1202.82 2066.06,1207.04 2085.32,1207.04 2140.47,1151.88 2140.47,1128 2157.05,1111.43 2218.15,1111.43 2228.51,1121.79 2228.51,1155.44 2364.38,1291.31 2412.08,1291.31 2445.76,1257.63 2481.68,1257.63 2524.24,1300.2 2524.24,1347.34 2483.9,1387.69 2483.9,1475.47 2631.4,1622.96 2631.4,1992.24 2533.53,2090.1 2533.53,2136.95 2387.34,2283.14 v1(2387.34,2330.09)
  Bottom Layer w5.9: U21.13@1379.77,1484.16 1379.77,1461.86 1388.79,1452.83 R181.1@1388.79,1429.77 1391.53,1432.5 R179.2@1442.71,1432.5 1442.71,1405.74 1437.27,1400.29 v1(1437.27,1397.02) ; R138.1@2360.37,2327.57 2361.64,2328.83 2386.08,2328.83 v1(2387.34,2330.09)
SW1: L5.1 U15.7
SW3: L3.1 U13.7
SW_PR1: R72.2 R77.2 U12.4 | length 88.4
  Top Layer w10: R77.2@2021.5,797.65 2023.2,799.35 R72.2@2058.37,799.35 ; U12.4@2022.21,850.74 2022.21,801.99 R77.2@2023.69,800.51
SW_ST: R65.1 TP5.1 U12.8 | length 124.8
  Top Layer w5.9: U12.8@2080.48,909.79 2109.67,909.79 2123.35,923.48 R65.1@2146.86,923.48 2169.46,923.48 TP5.1@2190.81,944.83
TCK: R104.2 U1.17 | length 755
  Top Layer w5.9: U1.17@1917.31,3186.81 v1(1917.31,3229.95)
  Bottom Layer w5.9: v1@1914.08,3229.95 v1@1915.69,3231.57 ; v1(1917.31,3229.95) 1954.28,3192.98 2083.43,3192.98 2141.31,3135.09 2141.31,2803.52 v1(2186.2,2758.63) ; v1@2186.2,2757.65 2204.57,2739.27 2204.57,2715.69 R104.2@2205.72,2714.54
TDI: R103.2 U1.16 | length 668.1
  Top Layer w5.9: U1.16@2051.17,3186.81 v1(2051.17,3229.95)
  L3_PWR1 w5.9: v1(2051.17,3229.95) 2051.17,3152.03 2131.31,3071.89 2131.31,2964.09 2168.01,2927.39 2204.4,2927.39 2235.1,2896.69 2235.1,2816.74 v1(2263.71,2788.13)
  Bottom Layer w5.9: R103.2@2263.32,2714.54 2263.52,2714.74 2263.52,2787.93 v1(2263.71,2788.13)
TDO_SOP0: R29.1 R130.2 U1.10 | length 4500.4
  Top Layer w5.9: R29.1@286.34,1686.28 286.34,1705.65 377.67,1796.98 377.67,2179.33 492.93,2294.6 492.93,2436.17 541.76,2484.99 702.41,2484.99 745.76,2528.34 1026.18,2528.34 1037.04,2517.48 1197.6,2517.48 1331.93,2651.81 1606.33,2651.81 1618.31,2639.83 1684.57,2639.83 1695.47,2628.94 1870.47,2628.94 1940.41,2558.99 1964.95,2558.99 1976.65,2570.68 1991.74,2570.68 2035.55,2614.48 2143.89,2614.48 2156.98,2627.58 2198.28,2627.58 2268.18,2697.48 v1(2298.52,2697.48) ; U1.10@2051.17,3336.41 2051.17,3289.34 2116.94,3223.57 2116.94,3056.54 2144.31,3029.18 2144.31,2925.09 2154.83,2914.57 2570.81,2914.57 2587.33,2898.05 2587.33,2779.8 v1@2571.17,2763.64
  Bottom Layer w5.9: R130.2@2280.17,2420.11 2294.21,2420.11 2300.36,2426.26 2300.36,2627.84 2314.62,2642.1 2314.62,2681.23 v1@2298.52,2697.33 ; v1(2298.52,2697.48) 2298.52,2719.58 2343.58,2764.63 2569.93,2764.63 v1(2570.92,2763.64)
TMS: R129.2 U1.11 | length 1732.1
  Top Layer w5.9: U1.11@1917.31,3336.41 1917.31,3311.68 1932.89,3296.09 2021.96,3296.09 2104.42,3213.63 2104.42,3048.88 2131.31,3022 2131.31,2893.09 2153.03,2871.37 2514.36,2871.37 2537.35,2848.38 2537.35,2742.18 2588.53,2691.01 v1(2588.53,2689.97)
  L3_PWR1 w5.9: v1(2198.65,2426.06) 2240.5,2467.92 2240.5,2495.29 2295.02,2549.81 2427.55,2549.81 2567.71,2689.97 v1(2588.53,2689.97)
  Bottom Layer w5.9: v1(2198.65,2426.06) 2201.92,2426.06 2207.09,2420.89 R129.2@2225.07,2420.89
TS3A_ENn: R25.1 U6.17 | length 48.4
  Top Layer w5.9: U6.17@910.26,1972.77 910.26,1956.33 925.79,1940.8 R25.1@925.79,1930.78
USB_5V: C47.2 J7.1 L4.1
USB_5V_D1: D5.2 L4.2
VBUS_1_DETECT: C67.2 R153.1 R154.2 U18.1 | length 124.7
  Bottom Layer w5.9: R153.1@1322.41,1956.64 1322.07,1956.29 R154.2@1322.07,1925.23 1322.23,1925.07 C67.2@1322.23,1893.26 1342.3,1893.26 1345.48,1896.44 U18.1@1381.98,1896.44
VCC_1V8: J2.1 J3.1 J17.2 J18.1 R18.2
VCC_3V3: C2.1 C6.1 C8.2 C57.1 C59.1 C61.1 C72.1 C76.1 C91.1 C92.1 C95.1 C96.1 L9.1 R4.2 R8.2 R11.1 R12.1 R23.1 R28.1 R36.2 R43.1 R92.2 R105.2 R107.2 R108.2 R128.2 R144.2 R145.1 R149.2 R157.2 R159.2 R161.2 R175.2 R177.1 R191.1 R194.2 R195.2 R202.2 R206.1 R210.2 R212.2 R215.2 R219.2 R221.1 TP8.1 U3.8 U6.5 U7.5 U9.4 U11.4 U16.8 U17.16 U19.8 U20.8 U21.5 U23.6 U24.1 U25.6 U26.6 | length 8203.2
  Top Layer w10: C8.2@221.61,2124.03 221.61,2098.37 221.65,2098.33 U7.5@221.65,2070.7 ; C8.2@221.9,2128.14 222.14,2127.9 222.14,2101.38 v1(222.68,2100.84) ; R11.1@249.33,2189.13 R12.1@297.37,2189.13 297.37,2157.57 v1(296.44,2156.64) ; R8.2@383.76,2327.22 v1(414.68,2327.19) ; U3.8@394.65,2386.58 455.01,2386.58 C2.1@455.06,2386.54 455.58,2386.01 455.58,2354.24 v1(456.1,2353.72) ; R28.1@582.99,1692.16 584.25,1693.42 v1(584.25,1723.95) ; U6.5@851.2,2122.38 C6.1@851.2,2171.44 ; C6.1@856.71,2177.07 v1(856.71,2202.28) ; v1@1001.29,967.07 v1(1001.58,966.79) ; R23.1@1074.94,2050.45 1075.15,2050.66 1106.91,2050.66 v1(1107.12,2050.87) ; v1(1885.65,1417.57) 1886.59,1416.63 2035.75,1416.63 2046.5,1405.88 R36.2@2065.54,1405.88 ; v1@2561.57,1505.9 2619.77,1564.09 v1(2828.31,1564.09)
  Top Layer w12: R4.2@391.3,2661.75 v1(391.31,2697.09) 467.31,2697.09 534.31,2630.09 997.31,2630.09 1035.64,2668.42 1206.19,2668.42 1287.62,2749.86 1473.15,2749.86 v1(1501.55,2721.47) ; TP8.1@1744.12,490.77 v1(1744.12,559.31)
  Top Layer w15: U9.4@900.64,1396.21 900.64,1365.72 911.26,1355.1 v1(911.26,1354.95) ; U11.4@957.91,967.07 v1@1001.29,967.07
  Top Layer w20: R92.2@350.7,400.57 351.69,400.57 360.39,391.87 360.39,390.88 419.6,331.67 v1(419.6,313.54)
  L3_PWR1 w10: v1(1937.47,2666.94) v1@1938.43,2665.99 ; v1@2079.55,2665.99 v1(2080.51,2665.03) ; v1(2316,2091.81) 2277.23,2091.81 2261.95,2107.09 2023.31,2107.09 1984.83,2068.62 1984.83,2030.92 1913.46,1959.55 1913.46,1850.61 1952.75,1811.32 2049.01,1811.32 2186.46,1673.87 2186.46,1520.18 2123.31,1457.03 2123.31,1346.23 2155.22,1314.31 2155.22,1249.18 2232.21,1172.19 2530.38,1172.19 v1(2640.82,1061.76)
  L3_PWR1 w20: v1(911.26,1354.95) 935.22,1378.9 1063.57,1378.9 1167.11,1275.36 v1(1255.05,1275.36)
  Bottom Layer w10: v1@280.99,1899.19 R157.2@281,1922.72 ; v1(419.6,313.54) 451.36,313.54 R219.2@451.62,313.8 452.19,314.37 R215.2@452.19,347.64 ; v1(538.21,1642.64) 538.44,1642.87 R175.2@578.98,1642.87 578.98,1665.72 563.41,1681.28 563.41,1775.54 567.43,1779.56 R161.2@567.43,1824.45 ; R221.1@644.35,270.83 644.35,299.83 v1(644.41,299.89) ; v1(828.01,576.25) 828.01,576.46 836.03,584.49 836.03,605.95 835.11,606.88 R202.2@835.11,610.79 ; v1(1152.21,1662.35) 1152.21,1690.62 C76.1@1152.48,1690.89 ; C76.1@1154.79,1690.89 1154.79,1710.23 1158.49,1713.93 1161.85,1717.29 U20.8@1161.85,1763.23 ; v1(1229.76,443.2) 1241.79,455.23 R206.1@1260.6,455.23 ; v1(1329.75,1711.6) 1355.54,1711.6 C72.1@1356.27,1712.33 1360.08,1708.51 U21.5@1360.08,1633.76 ; R212.2@1452.76,378.43 1452.76,411.69 R210.2@1453.33,412.26 1453.59,412.52 v1(1485.35,412.52) ; R177.1@1483.06,1531.27 1483.06,1527.29 1483.93,1526.42 1483.93,1516.15 v1(1494.04,1506.03) ; U16.8@1831.11,2731.78 1896.52,2731.78 C57.1@1898.74,2729.57 1899.81,2728.49 1899.81,2704.6 v1(1937.47,2666.94) ; v1(2063.6,2510.21) 2063.79,2510.03 C59.1@2096.9,2510.03 ; v1(2080.51,2665.03) 2081.29,2665.81 2113.48,2665.81 R108.2@2114.26,2666.59 ; C59.1@2096.9,2508.55 U17.16@2146.33,2508.55 ; R144.2@2139.97,2159.67 2164.37,2159.7 2174.03,2169.36 2174.03,2204.91 2231.26,2262.13 U19.8@2231.26,2293.08 C61.1@2231.26,2356.78 ; C61.1@2232.36,2358.37 v1(2232.36,2382.95) ; C61.1@2232.38,2356.78 2250.62,2356.78 2298.84,2308.57 2298.84,2283.31 2318.26,2263.89 2318.26,2180.06 2317.15,2178.96 2317.15,2092.96 v1(2316,2091.81) ; R191.1@2472.65,1087.16 2472.99,1086.82 2615.76,1086.82 v1(2640.82,1061.76) 2640.82,1032.66 2605.55,997.38 R194.2@2572.06,997.38 2571.49,996.81 R195.2@2571.49,963.55 ; L9.1@2486.52,1386.66 2486.52,1390.78 2485.8,1391.5 2485.8,1451.11 2540.58,1505.9 v1(2560.93,1505.9) ; R159.2@2778.48,1813.1 2778.48,1613.92 v1(2828.31,1564.09)
  Bottom Layer w15: R107.2@311.72,2669.53 363.74,2669.53 v1(391.31,2697.09) ; R149.2@1243.78,2002.52 1243.78,2027.69 1226.62,2044.86 v1(1226.62,2062.62) ; R128.2@1251.52,2440.51 1235.06,2440.51 1205.77,2411.22 1205.77,2274.52 1181.5,2250.25 1181.5,2107.74 v1(1226.62,2062.62) ; R145.1@1270.05,2062.63 v1(1226.62,2062.62) ; R105.2@1525.81,2706.06 R105.2@1525.9,2706.15
  Bottom Layer w20: v1@1002.59,966.79 1255.25,1219.45 1255.25,1275.16 v1(1255.05,1275.36) ; v1(1501.55,2721.47) 1501.55,2717.86 1513.26,2706.15 R105.2@1524.09,2706.15
  other v1: 1172.87,254.74 732.08,471.33 1713.89,563.14 2293.38,847.89 1255.25,1241.34 280.97,1899.17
